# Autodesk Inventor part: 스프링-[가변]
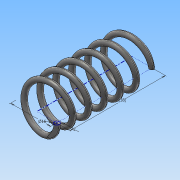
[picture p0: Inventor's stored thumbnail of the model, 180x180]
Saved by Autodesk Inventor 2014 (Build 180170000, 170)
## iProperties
Created: 2017-06
Part Number: 스프링-[가변]
Material: 강철, 탄소
Document SubType Name: Modeling
Designer: NET
Mass: 7.37477 g
Surface Area: 18.9866 cm^2
Volume: 0.937073 cm^3
Density: 7.87 g/cm^3
Appearance: 반연마
Author: NET
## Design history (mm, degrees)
sketch "스케치1"
  geometry: L1 (0, 0)-(8, 0); L2 (8, 0)-(8, 38); L3 (8, 38)-(0, 38); L4 (0, 38)-(0, 0); C1 r 1 at (8, 0)
  constraints: 8 end point, 2 parallel, 1 centre point, 1 coincident, 1 horizontal, 1 perpendicular
  dimensions: "d0" = 16 diameter of L2 L4; "d1" = 38 distance of L1.end L2.end (derived); "d2" = 2 diameter of C1
feature "코일1" sketch "스케치1" pitch "d3" = 10; turns "d5" = 6; dims "d4" = 38 (= d1), "d6" = 0, angle "d7" = 90 deg, angle "d8" = 90 deg, "d9" = 0, "d10" = 0
node "작업 평면1"
node "작업 평면2"
sketch "스케치2"
  geometry: L1 (-7, 0)-(-9, 0) reference; 1 further point
  constraints: 1 horizontal alignment
extrude "돌출1" cut sketch "스케치2" distance "d11" = 10; taper "d12" = 0 deg
sketch "스케치3"
  geometry: L1 (7, 0)-(9, 0) reference; 1 further point
  constraints: 1 horizontal alignment
extrude "돌출2" cut sketch "스케치3" distance "d13" = 10; taper "d14" = 0 deg
node "솔리드1"
node "절단 모서리 투영1"
node "절단 모서리 투영2"
